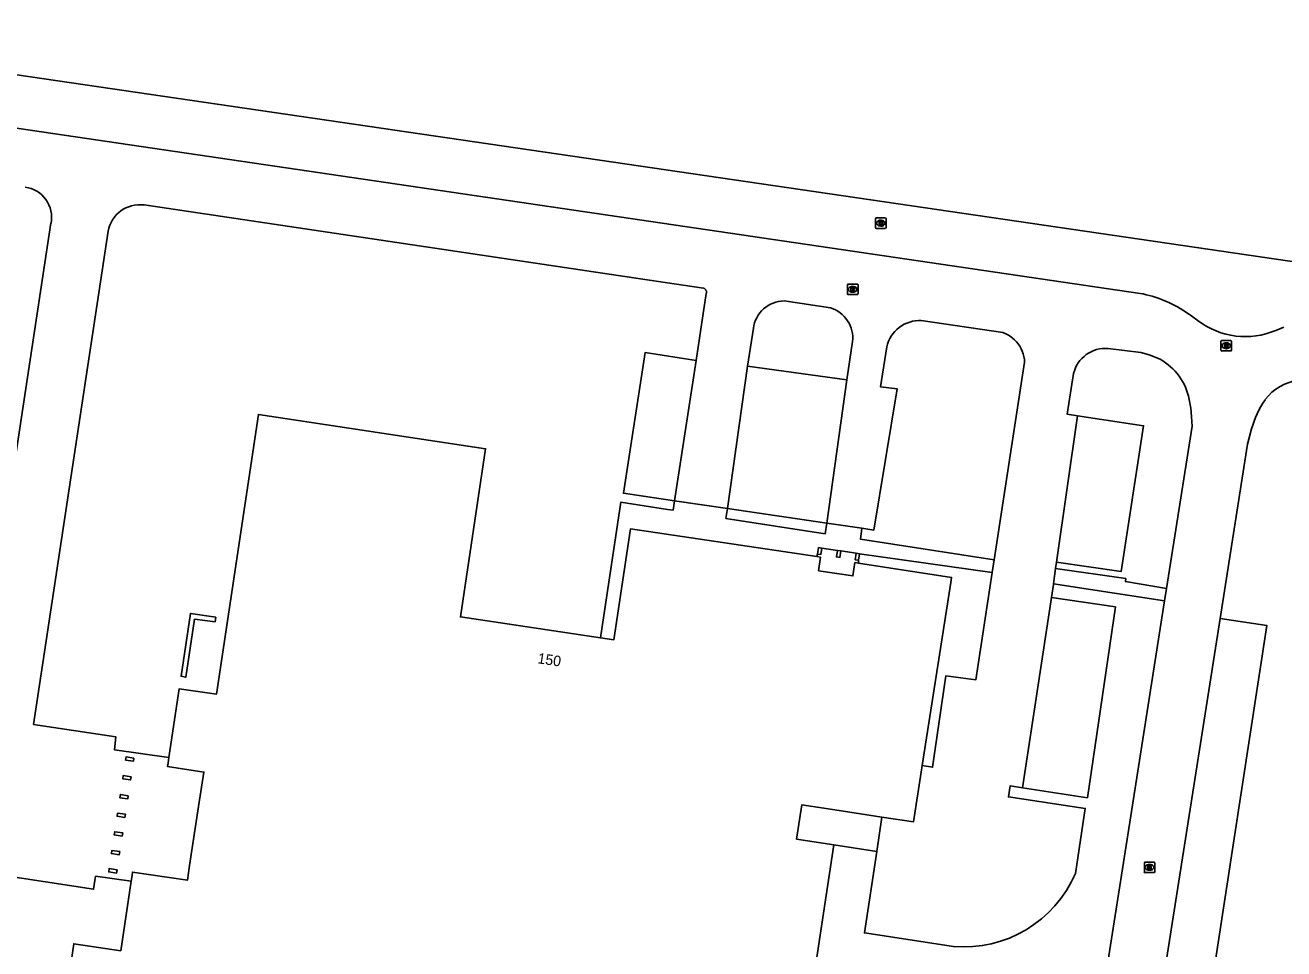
# Model space of a CAD drawing. Extents: x 156141 to 158132, y 385651 to 388399.
# Drawn here: x 156574.1 to 156694, y 385893.8 to 385981.8 of the extents above; entities that cross this region are included whole.
import ezdxf

# ---------------------------------------------------------------- set-up
doc = ezdxf.new("R2010")
doc.units = 0
for name, color, linetype in [('IMGEO_Brandkraan', 7, 'Continuous'), ('IMGEO_Grasland_overig', 7, 'Continuous'), ('IMGEO_Muur', 7, 'Continuous'), ('IMGEO_Pand', 7, 'Continuous'), ('IMGEO_Pand_nummerreeks', 7, 'Continuous'), ('IMGEO_Parkeervlak_open', 7, 'Continuous'), ('IMGEO_Rijbaan_lokaal_open', 7, 'Continuous'), ('IMGEO_Rioolput', 7, 'Continuous'), ('IMGEO_Voetpad_open', 7, 'Continuous')]:
    doc.layers.add(name, color=color, linetype=linetype)

msp = doc.modelspace()

# ---------------------------------------------------------------- linework, layer by layer
at = {"layer": 'IMGEO_Brandkraan'}
for p, q in [((156655.08, 385962.48), (156655.08, 385963.33)), ((156655.15, 385963.41), (156656, 385963.41)), ((156655.57, 385963.19), (156655.59, 385963.19)), ((156656.08, 385963.33), (156656.08, 385962.48)), ((156656, 385962.41), (156655.15, 385962.41)), ((156655.59, 385962.63), (156655.56, 385962.63))]:
    msp.add_line(p, q, dxfattribs=at)
for points in [[(156655.08, 385962.48), (156655.08, 385963.33)], [(156655.15, 385963.41), (156656, 385963.41)], [(156655.42, 385963.11), (156655.42, 385962.71), (156655.64, 385962.71)], [(156655.66, 385963.11), (156655.42, 385963.11)], [(156655.6, 385963.03), (156655.55, 385963.03), (156655.55, 385962.95)], [(156655.55, 385962.95), (156655.6, 385962.95)], [(156655.61, 385962.87), (156655.55, 385962.87), (156655.55, 385962.79)], [(156656.08, 385963.33), (156656.08, 385962.48)], [(156656, 385962.41), (156655.15, 385962.41)], [(156655.55, 385962.79), (156655.61, 385962.79)]]:
    msp.add_lwpolyline(points, dxfattribs=at)
for centre, radius, start, end in [((156655.15, 385963.33), 0.0765, 91.552, 178.448), ((156655.15, 385963.33), 0.0765, 91.552, 178.448), ((156655.6, 385962.99), 0.0379, 267.8285, 90.9355), ((156655.61, 385962.83), 0.0404, 269.8759, 90.5077), ((156655.66, 385962.96), 0.145, 59.4692, 91.5367), ((156655.69, 385963.01), 0.0922, 285.5137, 58.1501), ((156655.69, 385962.82), 0.105, 301.3115, 78.989), ((156656, 385963.33), 0.0765, 1.552, 88.448), ((156656, 385963.33), 0.0765, 1.552, 88.448), ((156655.15, 385962.48), 0.0765, 181.552, 268.448), ((156655.15, 385962.48), 0.0765, 181.552, 268.448), ((156655.64, 385962.96), 0.251, 268.6676, 293.5347), ((156656, 385962.48), 0.0765, 271.552, 358.448), ((156656, 385962.48), 0.0765, 271.552, 358.448)]:
    msp.add_arc(centre, radius, start, end, dxfattribs=at)
for centre, major_axis, ratio, start_param, end_param in [((156655.56, 385962.91), (-0.387, 0.002), 0.722429, 4.712389, 7.853982), ((156655.59, 385962.91), (-0.39, 0.002), 0.717154, 1.570796, 4.712389)]:
    msp.add_ellipse(centre, major_axis=major_axis, ratio=ratio, start_param=start_param, end_param=end_param, dxfattribs=at)
at = {"layer": 'IMGEO_Grasland_overig'}
msp.add_lwpolyline([(156874.88, 385935.88), (156869.91, 385941.02), (156868.37, 385942.51), (156867.15, 385943.55), (156865.04, 385945.13), (156863.64, 385946.03), (156861.71, 385947.12), (156859.45, 385948.19), (156855.65, 385949.54), (156852.46, 385950.28), (156850.75, 385950.55), (156847.01, 385950.81), (156823.49, 385951.07), (156739.66, 385952.67), (156453.02, 385994.66)], dxfattribs=at)
at = {"layer": 'IMGEO_Muur'}
msp.add_lwpolyline([(156592.22, 385925.35), (156592.15, 385924.92), (156590.18, 385925.16), (156589.35, 385919.64), (156588.91, 385919.73), (156589.8, 385925.72), (156592.22, 385925.35)], dxfattribs=at)
at = {"layer": 'IMGEO_Pand'}
for points in [[(156628.88, 385923.4), (156615.52, 385925.39), (156617.92, 385941.41), (156596.27, 385944.68), (156592.27, 385918.02), (156588.73, 385918.54), (156587.75, 385911.99)], [(156628.88, 385923.4), (156630.13, 385923.21), (156631.71, 385933.78), (156649.49, 385931.13)], [(156649.54, 385931.38), (156649.64, 385932), (156649.95, 385931.95)], [(156649.54, 385931.38), (156649.85, 385931.33), (156649.95, 385931.95)], [(156651.43, 385931.73), (156651.34, 385931.1), (156651.66, 385931.05), (156651.75, 385931.69)], [(156651.43, 385931.73), (156651.75, 385931.69)], [(156653.44, 385930.52), (156653.11, 385930.57), (156652.92, 385929.29), (156649.64, 385929.79), (156649.83, 385931.07), (156649.49, 385931.13)], [(156653.23, 385931.46), (156653.14, 385930.84), (156653.46, 385930.79)], [(156653.23, 385931.46), (156653.55, 385931.41)], [(156659.52, 385911.24), (156662.23, 385928.67), (156662.31, 385929.16), (156653.44, 385930.52)], [(156653.46, 385930.79), (156653.55, 385931.41)], [(156584.41, 385911.93), (156583.66, 385912.05), (156583.61, 385911.74), (156584.36, 385911.63), (156584.41, 385911.93)], [(156587.75, 385911.99), (156587.67, 385911.44), (156587.62, 385911.13), (156591.08, 385910.61), (156590.58, 385907.33), (156589.72, 385901.69), (156589.51, 385900.29), (156584.27, 385901.07), (156584.23, 385900.75), (156584.15, 385900.22)], [(156584.14, 385910.16), (156583.39, 385910.27), (156583.34, 385909.96), (156584.09, 385909.85), (156584.14, 385910.16)], [(156655.67, 385906.31), (156658.68, 385905.85), (156659.42, 385910.59), (156659.52, 385911.24)], [(156583.87, 385908.35), (156583.12, 385908.47), (156583.07, 385908.16), (156583.82, 385908.05), (156583.87, 385908.35)], [(156583.6, 385906.59), (156582.85, 385906.7), (156582.8, 385906.39), (156583.56, 385906.28), (156583.6, 385906.59)], [(156651.09, 385903.67), (156647.54, 385904.21), (156648.04, 385907.47), (156651.59, 385906.93), (156655.67, 385906.31)], [(156583.34, 385904.8), (156582.58, 385904.92), (156582.54, 385904.61), (156583.29, 385904.5), (156583.34, 385904.8)], [(156583.07, 385903.03), (156582.32, 385903.14), (156582.27, 385902.83), (156583.02, 385902.72), (156583.07, 385903.03)], [(156649.37, 385892.33), (156651.09, 385903.67)], [(156582.81, 385901.28), (156582.05, 385901.4), (156582.01, 385901.09), (156582.76, 385900.98), (156582.81, 385901.28)], [(156583.16, 385893.58), (156584.15, 385900.22)]]:
    msp.add_lwpolyline(points, dxfattribs=at)
at = {"layer": 'IMGEO_Parkeervlak_open'}
for points in [[(156637.97, 385949.81), (156633.11, 385950.58), (156631.05, 385937.17), (156635.92, 385936.45)], [(156652.32, 385947.98), (156642.87, 385949.28)], [(156672.31, 385930.59), (156678.46, 385929.71), (156680.61, 385943.6), (156674.31, 385944.56)], [(156650.43, 385934.32), (156640.96, 385935.71)], [(156669.07, 385909.1), (156675.26, 385908.15), (156677.92, 385926.34), (156671.82, 385927.23)], [(156687.9, 385925.24), (156692.35, 385924.56), (156686.07, 385883.56), (156681.44, 385884.26)]]:
    msp.add_lwpolyline(points, dxfattribs=at)
at = {"layer": 'IMGEO_Rijbaan_lokaal_open'}
for points in [[(156533.26, 385977.84), (156680.28, 385956.22)], [(156637.97, 385949.81), (156638.94, 385956.2), (156638.95, 385956.24), (156638.95, 385956.27), (156638.96, 385956.3), (156638.96, 385956.34), (156638.96, 385956.37), (156638.95, 385956.41), (156638.95, 385956.44), (156638.94, 385956.47), (156638.92, 385956.5), (156638.91, 385956.53), (156638.89, 385956.56), (156638.87, 385956.59), (156638.85, 385956.61), (156638.82, 385956.64), (156638.79, 385956.66), (156638.77, 385956.68), (156638.74, 385956.69), (156638.7, 385956.71), (156638.67, 385956.72), (156634.16, 385957.37), (156585.38, 385964.65)], [(156558.49, 385917.22), (156557.76, 385912.31), (156568.57, 385910.68), (156569.08, 385913.95), (156576.51, 385962.92)], [(156581.96, 385962.14), (156574.86, 385915.14), (156582.7, 385913.96), (156582.55, 385912.73), (156587.75, 385911.99)], [(156652.32, 385947.98), (156652.88, 385951.63), (156652.89, 385951.89), (156652.89, 385952.15), (156652.86, 385952.4), (156652.81, 385952.66), (156652.74, 385952.91), (156652.65, 385953.15), (156652.54, 385953.39), (156652.4, 385953.61), (156652.25, 385953.82), (156652.08, 385954.02), (156651.9, 385954.2), (156651.7, 385954.37), (156651.49, 385954.52), (156651.26, 385954.65), (156651.03, 385954.76), (156650.78, 385954.85), (156646.35, 385955.5), (156646.08, 385955.49), (156645.82, 385955.45), (156645.56, 385955.39), (156645.3, 385955.3), (156645.06, 385955.19), (156644.83, 385955.06), (156644.61, 385954.91), (156644.4, 385954.74), (156644.21, 385954.55), (156644.04, 385954.35), (156643.89, 385954.13), (156643.75, 385953.9), (156643.64, 385953.66), (156643.55, 385953.41), (156643.48, 385953.15), (156643.44, 385952.89), (156642.87, 385949.28)], [(156684.59, 385954.47), (156685.19, 385954.04), (156685.8, 385953.6)], [(156653.76, 385933.84), (156654.9, 385933.67), (156657.13, 385947.11), (156655.53, 385947.32), (156656.13, 385951.12), (156656.21, 385951.39), (156656.3, 385951.65), (156656.42, 385951.91), (156656.56, 385952.15), (156656.73, 385952.38), (156656.91, 385952.6), (156657.11, 385952.79), (156657.32, 385952.98), (156657.55, 385953.14), (156657.8, 385953.28), (156658.05, 385953.39), (156658.32, 385953.49), (156658.59, 385953.56), (156658.87, 385953.61), (156659.15, 385953.63), (156659.43, 385953.63), (156667.18, 385952.5), (156667.42, 385952.4), (156667.66, 385952.28), (156667.89, 385952.13), (156668.1, 385951.98), (156668.3, 385951.8), (156668.49, 385951.61), (156668.65, 385951.4), (156668.8, 385951.18), (156668.93, 385950.94), (156669.05, 385950.7), (156669.14, 385950.45), (156669.2, 385950.19), (156669.25, 385949.93), (156669.27, 385949.66), (156666.38, 385930.84)], [(156693.21, 385952.69), (156693.97, 385952.99)], [(156674.31, 385944.56), (156673.34, 385944.7), (156673.93, 385948.59), (156674.01, 385948.85), (156674.11, 385949.11), (156674.23, 385949.36), (156674.38, 385949.59), (156674.54, 385949.81), (156674.73, 385950.02), (156674.93, 385950.21), (156675.14, 385950.38), (156675.37, 385950.53), (156675.61, 385950.66), (156675.86, 385950.77), (156676.13, 385950.86), (156676.39, 385950.92), (156676.67, 385950.96), (156676.94, 385950.98), (156677.22, 385950.97), (156680.33, 385950.59), (156681.15, 385950.36), (156682.19, 385949.94)], [(156635.92, 385936.45), (156637.97, 385949.81)], [(156642.87, 385949.28), (156640.96, 385935.71)], [(156650.43, 385934.32), (156652.32, 385947.98)], [(156684.96, 385946.12), (156685.1, 385945.29), (156685.18, 385944.44), (156685.23, 385943.58), (156682.79, 385928.11)], [(156674.31, 385944.56), (156672.31, 385930.59)], [(156690.89, 385943.31), (156690.69, 385942.57), (156690.51, 385941.84), (156687.9, 385925.24)], [(156640.96, 385935.71), (156635.92, 385936.45)], [(156653.76, 385933.84), (156650.43, 385934.32)], [(156666.19, 385929.63), (156666.38, 385930.84)], [(156672.22, 385929.99), (156672.31, 385930.59)], [(156666.19, 385929.63), (156664.61, 385919.39), (156661.75, 385919.77), (156660.5, 385911.06), (156659.52, 385911.24)], [(156672.22, 385929.99), (156672.01, 385928.53)], [(156672.01, 385928.53), (156672.01, 385928.47), (156671.82, 385927.23)], [(156682.6, 385926.92), (156682.79, 385928.11)], [(156671.82, 385927.23), (156669.07, 385909.1)], [(156676.07, 385885.71), (156677.19, 385892.5), (156679.28, 385905.83), (156682.6, 385926.92)], [(156681.44, 385884.26), (156687.9, 385925.24)], [(156669.07, 385909.1), (156667.89, 385909.28), (156667.73, 385908.23), (156675.04, 385907.14), (156674.11, 385900.94)], [(156584.15, 385900.22), (156580.76, 385900.68), (156580.57, 385899.44), (156567.22, 385901.48), (156567.95, 385906.56), (156557.13, 385908.2), (156556.37, 385903.42), (156556.37, 385903.39)], [(156655.67, 385906.31), (156655.18, 385903.04)], [(156662.48, 385893.98), (156654.01, 385895.27), (156655.18, 385903.04)]]:
    msp.add_lwpolyline(points, dxfattribs=at)
for centre, radius, start, end in [((156573.67, 385963.47), 2.9, 348.9615, 82.3664), ((156584.98, 385961.6), 3.07, 82.6239, 169.9766), ((156678, 385944.4), 12.04, 56.7659, 79.0408), ((156690.29, 385959.55), 7.45, 232.9597, 293.0094), ((156679.37, 385944.99), 5.7, 11.4143, 60.3333), ((156695.99, 385943.22), 4.77, 97.1066, 142.9646), ((156699.27, 385941.12), 8.65, 144.9843, 165.3819), ((156663.47, 385905.52), 11.58, 265.0936, 336.7238)]:
    msp.add_arc(centre, radius, start, end, dxfattribs=at)
at = {"layer": 'IMGEO_Rioolput'}
for p, q in [((156652.4, 385956.17), (156652.4, 385957.03)), ((156652.47, 385957.1), (156653.32, 385957.1)), ((156652.89, 385956.88), (156652.91, 385956.88)), ((156653.4, 385957.03), (156653.4, 385956.17)), ((156653.32, 385956.1), (156652.47, 385956.1)), ((156652.91, 385956.32), (156652.88, 385956.32)), ((156687.98, 385950.8), (156687.98, 385951.66)), ((156688.06, 385951.73), (156688.91, 385951.73)), ((156688.47, 385951.51), (156688.5, 385951.51)), ((156688.49, 385950.95), (156688.47, 385950.95)), ((156688.98, 385951.66), (156688.98, 385950.8)), ((156688.91, 385950.73), (156688.06, 385950.73)), ((156680.68, 385901.09), (156680.68, 385901.94)), ((156680.75, 385902.02), (156681.6, 385902.02)), ((156681.16, 385901.8), (156681.19, 385901.8)), ((156681.68, 385901.94), (156681.68, 385901.09)), ((156681.6, 385901.02), (156680.75, 385901.02)), ((156681.19, 385901.24), (156681.16, 385901.24))]:
    msp.add_line(p, q, dxfattribs=at)
for points in [[(156652.4, 385956.17), (156652.4, 385957.03)], [(156652.47, 385957.1), (156653.32, 385957.1)], [(156653.4, 385957.03), (156653.4, 385956.17)], [(156653.32, 385956.1), (156652.47, 385956.1)], [(156652.99, 385956.8), (156652.73, 385956.8), (156652.73, 385956.4)], [(156652.73, 385956.4), (156652.86, 385956.4), (156652.86, 385956.56), (156652.87, 385956.56)], [(156652.91, 385956.72), (156652.86, 385956.72), (156652.86, 385956.64)], [(156652.86, 385956.64), (156652.91, 385956.64)], [(156652.92, 385956.53), (156652.99, 385956.4), (156653.13, 385956.4), (156653.06, 385956.53)], [(156687.98, 385950.8), (156687.98, 385951.66)], [(156688.06, 385951.73), (156688.91, 385951.73)], [(156688.57, 385951.43), (156688.32, 385951.43), (156688.32, 385951.03)], [(156688.32, 385951.03), (156688.44, 385951.03), (156688.44, 385951.19), (156688.45, 385951.19)], [(156688.5, 385951.35), (156688.44, 385951.35), (156688.44, 385951.27)], [(156688.44, 385951.27), (156688.49, 385951.27)], [(156688.5, 385951.16), (156688.57, 385951.03), (156688.71, 385951.03), (156688.65, 385951.16)], [(156688.98, 385951.66), (156688.98, 385950.8)], [(156688.91, 385950.73), (156688.06, 385950.73)], [(156680.68, 385901.09), (156680.68, 385901.94)], [(156680.75, 385902.02), (156681.6, 385902.02)], [(156681.26, 385901.71), (156681.01, 385901.72), (156681.01, 385901.32)], [(156681.68, 385901.94), (156681.68, 385901.09)], [(156681.6, 385901.02), (156680.75, 385901.02)], [(156681.01, 385901.32), (156681.14, 385901.32), (156681.14, 385901.48), (156681.15, 385901.48)], [(156681.19, 385901.64), (156681.14, 385901.64), (156681.14, 385901.55)], [(156681.14, 385901.55), (156681.19, 385901.55)], [(156681.19, 385901.45), (156681.27, 385901.32), (156681.4, 385901.32), (156681.34, 385901.44)]]:
    msp.add_lwpolyline(points, dxfattribs=at)
for centre, radius, start, end in [((156652.47, 385957.03), 0.0765, 91.552, 178.448), ((156652.47, 385957.03), 0.0765, 91.552, 178.448), ((156653.32, 385957.03), 0.0765, 1.552, 88.448), ((156653.32, 385957.03), 0.0765, 1.552, 88.448), ((156652.47, 385956.18), 0.0765, 181.552, 268.448), ((156652.47, 385956.18), 0.0765, 181.552, 268.448), ((156652.87, 385956.51), 0.0533, 26.0293, 88.6989), ((156652.92, 385956.62), 0.0964, 77.0061, 93.1865), ((156652.89, 385956.83), 0.19, 274.7715, 282.9687), ((156652.93, 385956.68), 0.0378, 276.6634, 79.6772), ((156652.99, 385956.69), 0.109, 350.3612, 89.416), ((156652.98, 385956.69), 0.112, 277.5842, 350.9817), ((156652.97, 385956.47), 0.108, 29.5134, 73.7905), ((156653.32, 385956.18), 0.0765, 271.552, 358.448), ((156653.32, 385956.18), 0.0765, 271.552, 358.448), ((156688.06, 385951.65), 0.0765, 91.552, 178.448), ((156688.06, 385951.65), 0.0765, 91.552, 178.448), ((156688.45, 385951.14), 0.0533, 26.0293, 88.6989), ((156688.48, 385951.46), 0.19, 274.7715, 282.9687), ((156688.5, 385951.25), 0.0964, 77.0061, 93.1865), ((156688.52, 385951.31), 0.0378, 276.6634, 79.6772), ((156688.57, 385951.32), 0.109, 350.3612, 89.416), ((156688.57, 385951.32), 0.112, 277.5842, 350.9817), ((156688.55, 385951.1), 0.108, 29.5134, 73.7905), ((156688.91, 385951.65), 0.0765, 1.552, 88.448), ((156688.91, 385951.65), 0.0765, 1.552, 88.448), ((156688.06, 385950.8), 0.0765, 181.552, 268.448), ((156688.06, 385950.8), 0.0765, 181.552, 268.448), ((156688.91, 385950.8), 0.0765, 271.552, 358.448), ((156688.91, 385950.8), 0.0765, 271.552, 358.448), ((156680.75, 385901.94), 0.0765, 91.552, 178.448), ((156680.75, 385901.94), 0.0765, 91.552, 178.448), ((156681.26, 385901.61), 0.109, 350.3612, 89.416), ((156681.6, 385901.94), 0.0765, 1.552, 88.448), ((156681.6, 385901.94), 0.0765, 1.552, 88.448), ((156680.75, 385901.09), 0.0765, 181.552, 268.448), ((156680.75, 385901.09), 0.0765, 181.552, 268.448), ((156681.15, 385901.43), 0.0533, 26.0293, 88.6989), ((156681.2, 385901.54), 0.0964, 77.0061, 93.1865), ((156681.17, 385901.74), 0.19, 274.7715, 282.9687), ((156681.21, 385901.6), 0.0378, 276.6634, 79.6772), ((156681.26, 385901.6), 0.112, 277.5842, 350.9817), ((156681.25, 385901.39), 0.108, 29.5134, 73.7905), ((156681.6, 385901.09), 0.0765, 271.552, 358.448), ((156681.6, 385901.09), 0.0765, 271.552, 358.448)]:
    msp.add_arc(centre, radius, start, end, dxfattribs=at)
for centre, major_axis, ratio, start_param, end_param in [((156652.88, 385956.6), (-0.387, 0.002), 0.722429, 4.712389, 7.853982), ((156652.91, 385956.6), (-0.39, 0.002), 0.717154, 1.570796, 4.712389), ((156688.47, 385951.23), (-0.387, 0.002), 0.722429, 4.712389, 7.853982), ((156688.49, 385951.23), (-0.39, 0.002), 0.717154, 1.570796, 4.712389), ((156681.16, 385901.52), (-0.387, 0.002), 0.722429, 4.712389, 7.853982), ((156681.19, 385901.52), (-0.39, 0.002), 0.717154, 1.570796, 4.712389)]:
    msp.add_ellipse(centre, major_axis=major_axis, ratio=ratio, start_param=start_param, end_param=end_param, dxfattribs=at)
at = {"layer": 'IMGEO_Voetpad_open'}
for points in [[(156635.92, 385936.45), (156635.78, 385935.55), (156635.26, 385935.63), (156630.8, 385936.32), (156628.88, 385923.4)], [(156640.96, 385935.71), (156640.82, 385934.78), (156650.28, 385933.32), (156650.43, 385934.32)], [(156666.38, 385930.84), (156653.62, 385932.81), (156653.76, 385933.84)], [(156649.95, 385931.95), (156651.43, 385931.73)], [(156651.75, 385931.69), (156653.23, 385931.46)], [(156649.49, 385931.13), (156649.54, 385931.38)], [(156653.44, 385930.52), (156653.46, 385930.79)], [(156653.55, 385931.41), (156666.19, 385929.63)], [(156682.79, 385928.11), (156678.87, 385928.76), (156678.91, 385929.04), (156672.22, 385929.99)], [(156672.01, 385928.53), (156682.6, 385926.92)], [(156655.18, 385903.04), (156651.09, 385903.67)], [(156604.15, 385874.63), (156588.33, 385877), (156586.56, 385865.03), (156574.62, 385866.8), (156578.68, 385894.24), (156583.16, 385893.58)]]:
    msp.add_lwpolyline(points, dxfattribs=at)

# ---------------------------------------------------------------- texts
at = {"layer": 'IMGEO_Pand_nummerreeks'}
msp.add_text('150', height=1, rotation=351.5202, dxfattribs=at).set_placement((156622.82, 385920.98))

doc.saveas('drawing.dxf')
